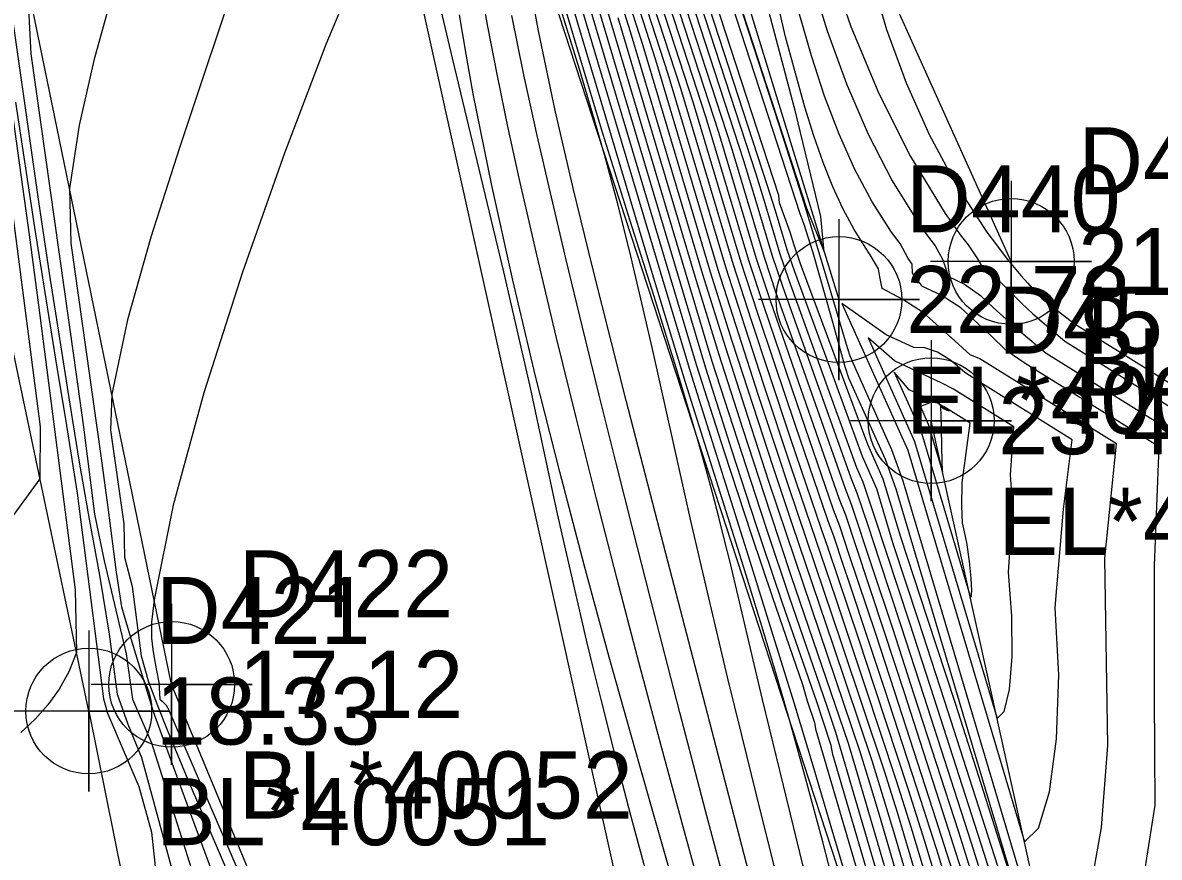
# Model space of a CAD drawing. Extents: x 2356077 to 2359823, y 225951 to 227822.
# Drawn here: x 2356590.47 to 2356632.82, y 227007.67 to 227038.77 of the extents above; entities that cross this region are included whole.
import ezdxf

# ---------------------------------------------------------------- set-up
doc = ezdxf.new("R2010")
doc.units = 0
for name, color, linetype in [('DTM Contours Major', 7, 'Continuous'), ('DTM Contours Minor', 7, 'Continuous'), ('Exist DTM Breakline', 7, 'Continuous'), ('Exist DTM Breakline Cogo Comment', 7, 'Continuous'), ('Exist DTM Breakline Cogo Elevation', 7, 'Continuous'), ('Exist DTM Breakline Cogo Number', 7, 'Continuous'), ('Exist DTM Breakline Cogo Point CELL', 7, 'Continuous'), ('Exist DTM Drainline', 7, 'Continuous'), ('PH Exist DTM Breakline', 7, 'Continuous')]:
    doc.layers.add(name, color=color, linetype=linetype)

msp = doc.modelspace()

# ---------------------------------------------------------------- linework, layer by layer
at = {"layer": 'DTM Contours Major'}
for points in [[(2356626.812, 227007.333), (2356624.819, 227013.515), (2356623.85, 227016.494), (2356622.909, 227019.356), (2356622.297, 227021.404), (2356621.759, 227022.605), (2356620.577, 227025.837), (2356619.238, 227029.489), (2356618.957, 227030.309), (2356618.523, 227031.766), (2356618.228, 227032.691), (2356612.291, 227050.925)], [(2356629.27, 226988.349), (2356629.959, 226992.149), (2356629.673, 226992.804), (2356629.314, 226993.528), (2356629.17, 226994.28), (2356628.968, 226994.95), (2356628.667, 226995.53), (2356628.358, 226996.17), (2356626.282, 227003.244), (2356625.118, 227007.164), (2356624.401, 227009.408), (2356622.955, 227013.857), (2356622.255, 227015.991), (2356621.27, 227018.937), (2356620.919, 227020.011), (2356620.688, 227020.62), (2356619.323, 227024.568), (2356618.094, 227028.184), (2356617.524, 227029.906), (2356615.937, 227035.231), (2356611.325, 227049.397)], [(2356589.642, 227042.057), (2356591.051, 227032.107), (2356591.458, 227029.439), (2356591.872, 227026.773), (2356592.222, 227024.561), (2356592.577, 227022.393), (2356592.945, 227020.266), (2356593.334, 227018.181), (2356593.695, 227015.987), (2356593.982, 227013.751), (2356594.382, 227012.627), (2356594.894, 227011.389), (2356595.263, 227010.019), (2356596.027, 227007.227), (2356596.416, 227005.784), (2356597.076, 227003.228), (2356597.704, 227000.624), (2356598.006, 226998.264), (2356598.808, 226990.945)], [(2356621.331, 226990.471), (2356620.981, 226992.712), (2356620.52, 226995.046), (2356619.978, 226997.442), (2356619.383, 226999.871), (2356618.764, 227002.302), (2356617.178, 227008.439), (2356614.034, 227020.515), (2356612.957, 227024.688), (2356612.404, 227026.855), (2356611.695, 227029.668), (2356610.99, 227032.561), (2356610.315, 227035.506), (2356609.692, 227038.475), (2356609.148, 227041.44)], [(2356620.446, 227041.168), (2356621.329, 227038.631), (2356622.374, 227036.136), (2356623.553, 227033.782), (2356624.843, 227031.665), (2356625.124, 227031.262), (2356625.408, 227030.873), (2356625.697, 227030.498), (2356626.051, 227029.975), (2356626.327, 227029.497), (2356626.867, 227029.144), (2356627.272, 227028.725), (2356627.686, 227028.316), (2356628.108, 227027.917), (2356629.303, 227026.9), (2356635.813, 227022.844)], [(2356625.118, 226990.059), (2356625.172, 226991.585), (2356625.114, 226993.197), (2356625.091, 226993.445), (2356625.048, 226993.939), (2356624.654, 226996.663), (2356620.041, 227012.387), (2356619.989, 227012.675), (2356619.718, 227013.487), (2356619.538, 227014.09), (2356618.423, 227017.334), (2356617.637, 227019.664), (2356616.615, 227022.761), (2356615.572, 227026.025), (2356611.23, 227040.614)], [(2356627.285, 226990.072), (2356627.444, 226991.194), (2356627.654, 226992.353), (2356627.554, 226992.793), (2356627.275, 226993.331), (2356627.145, 226993.984), (2356627.071, 226994.51), (2356626.96, 226995.021), (2356626.852, 226995.234), (2356622.965, 227008.487), (2356622.55, 227009.883), (2356622.117, 227011.259), (2356620.677, 227015.549), (2356619.139, 227020.094), (2356618.433, 227022.216), (2356617.697, 227024.466), (2356616.908, 227026.908), (2356616.099, 227029.474), (2356613.589, 227037.908), (2356612.935, 227039.955)], [(2356623.704, 227023.16), (2356626.776, 227012.842), (2356627.046, 227013.098), (2356627.239, 227013.917), (2356627.338, 227015.153), (2356627.33, 227016.659), (2356627.199, 227018.292), (2356627.368, 227020.71), (2356627.277, 227021.924), (2356627.403, 227023.71), (2356625.158, 227025.109), (2356624.72, 227025.344), (2356622.959, 227026.169), (2356621.971, 227027.028), (2356623.704, 227023.16)]]:
    msp.add_lwpolyline(points, dxfattribs=at)
at = {"layer": 'DTM Contours Minor'}
for points in [[(2356611.415, 227058.105), (2356611.609, 227057.126), (2356612.086, 227055.298), (2356613.972, 227049.36), (2356619.67, 227031.862), (2356620.339, 227030.237), (2356620.206, 227031.548), (2356619.267, 227035.452), (2356615.488, 227049.719), (2356613.555, 227055.854), (2356615.374, 227056.83), (2356611.817, 227058.329), (2356611.415, 227058.105)], [(2356627.237, 227004.773), (2356626.311, 227007.775), (2356624.438, 227013.594), (2356623.526, 227016.398), (2356622.655, 227019.028), (2356622.226, 227020.34), (2356621.786, 227021.65), (2356621.552, 227022.186), (2356620.526, 227025.03), (2356619.013, 227029.207), (2356618.685, 227030.179), (2356618.131, 227032.039), (2356617.794, 227033.127), (2356611.142, 227053.555)], [(2356626.691, 227005.425), (2356625.823, 227008.197), (2356624.062, 227013.664), (2356623.205, 227016.297), (2356622.392, 227018.743), (2356621.984, 227019.996), (2356621.569, 227021.24), (2356621.337, 227021.792), (2356619.249, 227027.648), (2356618.792, 227028.937), (2356618.394, 227030.112), (2356617.725, 227032.361), (2356617.337, 227033.631), (2356610.893, 227053.422)], [(2356630.311, 226988.925), (2356630.88, 226992.059), (2356630.519, 226992.812), (2356630.153, 226993.591), (2356629.979, 226994.385), (2356629.711, 226995.156), (2356628.936, 226996.651), (2356628.636, 226997.649), (2356627.36, 227001.998), (2356626.161, 227006.025), (2356625.347, 227008.604), (2356623.694, 227013.727), (2356622.891, 227016.19), (2356622.125, 227018.492), (2356621.356, 227020.822), (2356621.124, 227021.398), (2356619.051, 227027.271), (2356618.551, 227028.699), (2356618.111, 227030.022), (2356617.319, 227032.68), (2356616.879, 227034.138), (2356610.734, 227053.011)], [(2356629.791, 226988.638), (2356630.42, 226992.105), (2356630.095, 226992.809), (2356629.733, 226993.562), (2356629.574, 226994.334), (2356629.34, 226995.053), (2356628.997, 226995.714), (2356628.645, 226996.404), (2356626.82, 227002.624), (2356625.636, 227006.605), (2356624.871, 227009.009), (2356623.323, 227013.793), (2356622.572, 227016.09), (2356621.508, 227019.291), (2356621.137, 227020.418), (2356620.906, 227021.007), (2356619.377, 227025.387), (2356618.324, 227028.44), (2356617.815, 227029.97), (2356616.407, 227034.687), (2356610.598, 227052.532)], [(2356632.386, 226990.036), (2356632.711, 226991.826), (2356632.232, 226992.787), (2356631.801, 226993.685), (2356631.539, 226994.644), (2356631.141, 226995.676), (2356630.047, 226997.786), (2356629.946, 226998.035), (2356629.913, 226998.396), (2356629.592, 226999.277), (2356629.488, 226999.576), (2356627.346, 227006.768), (2356626.29, 227010.101), (2356625.224, 227013.397), (2356624.19, 227016.563), (2356623.188, 227019.6), (2356622.537, 227021.76), (2356621.96, 227023.05), (2356619.458, 227029.792), (2356619.216, 227030.481), (2356619.071, 227030.97), (2356618.673, 227032.063), (2356618.64, 227032.327), (2356612.488, 227051.222)], [(2356628.749, 226988.06), (2356629.498, 226992.19), (2356629.251, 226992.799), (2356628.896, 226993.493), (2356628.765, 226994.224), (2356628.596, 226994.848), (2356628.338, 226995.344), (2356628.067, 226995.945), (2356625.248, 227005.545), (2356624.603, 227007.712), (2356623.935, 227009.798), (2356622.589, 227013.92), (2356621.938, 227015.894), (2356621.311, 227017.77), (2356621.026, 227018.613), (2356620.703, 227019.6), (2356620.469, 227020.238), (2356619.26, 227023.763), (2356618.478, 227026.084), (2356617.861, 227027.93), (2356617.236, 227029.83), (2356615.466, 227035.775), (2356611.129, 227049.1)], [(2356614.528, 227046.719), (2356619.432, 227031.658), (2356619.571, 227031.259), (2356619.73, 227030.789), (2356619.911, 227030.209), (2356620.595, 227027.797), (2356621.107, 227025.959), (2356621.244, 227025.542), (2356622.602, 227022.508), (2356623.005, 227021.395), (2356628.693, 227002.292)], [(2356614.819, 227046.725), (2356618.644, 227034.976), (2356619.571, 227032.059), (2356620.413, 227029.299), (2356621.159, 227026.796), (2356621.277, 227026.391), (2356621.409, 227026.067), (2356622.845, 227022.862), (2356623.267, 227021.698), (2356627.902, 227006.131)], [(2356603.142, 227041.249), (2356601.769, 227037.958), (2356600.222, 227033.916), (2356598.654, 227029.474), (2356597.22, 227024.984), (2356596.073, 227020.796), (2356595.369, 227017.263), (2356595.271, 227016.435), (2356595.262, 227015.837), (2356595.314, 227015.413), (2356595.383, 227015.021), (2356595.459, 227014.631), (2356595.537, 227014.182), (2356595.576, 227013.567), (2356595.665, 227013.492), (2356595.743, 227013.417), (2356595.81, 227013.337), (2356595.867, 227013.251), (2356595.915, 227013.156), (2356601.009, 227001.351)], [(2356618.392, 226987.922), (2356617.47, 226991.783), (2356614.336, 227004.774), (2356613.131, 227009.221), (2356612.569, 227011.373), (2356612.022, 227013.546), (2356611.751, 227014.648), (2356611.483, 227015.766), (2356610.402, 227020.473), (2356609.361, 227025.273), (2356608.402, 227029.494), (2356606.482, 227037.446), (2356605.533, 227041.515)], [(2356623.747, 226990.674), (2356623.688, 226991.839), (2356623.575, 226993.042), (2356623.411, 226994.29), (2356623.202, 226995.588), (2356622.95, 226996.943), (2356622.662, 226998.36), (2356622.133, 227000.76), (2356621.544, 227003.259), (2356620.918, 227005.781), (2356620.281, 227008.247), (2356619.654, 227010.582), (2356619.064, 227012.707), (2356618.562, 227014.451), (2356618.065, 227016.115), (2356617.326, 227018.507), (2356615.164, 227025.366), (2356614.016, 227029.166), (2356610.39, 227041.347)], [(2356628.546, 226989.523), (2356629.037, 226992.23), (2356628.828, 226992.794), (2356628.486, 226993.453), (2356628.36, 226994.166), (2356628.222, 226994.75), (2356628.01, 226995.159), (2356627.774, 226995.733), (2356624.677, 227006.281), (2356624.09, 227008.253), (2356623.473, 227010.18), (2356622.225, 227013.981), (2356621.623, 227015.801), (2356620.488, 227019.185), (2356620.249, 227019.864), (2356619.095, 227023.253), (2356618.284, 227025.685), (2356617.625, 227027.676), (2356616.95, 227029.746), (2356614.995, 227036.315), (2356613.371, 227041.316)], [(2356598.672, 227041.19), (2356596.305, 227034.112), (2356595.244, 227030.783), (2356594.377, 227027.696), (2356593.788, 227024.93), (2356593.741, 227023.59), (2356594.236, 227020.096), (2356594.26, 227018.853), (2356594.548, 227017.759), (2356594.879, 227015.181), (2356595.156, 227014.203), (2356595.489, 227013.327), (2356595.851, 227012.42), (2356596.675, 227010.441), (2356598.524, 227006.146)], [(2356622.979, 226989.938), (2356622.876, 226991.413), (2356622.693, 226992.944), (2356622.441, 226994.53), (2356622.131, 226996.172), (2356621.775, 226997.871), (2356621.383, 226999.625), (2356620.825, 227002.034), (2356620.242, 227004.484), (2356619.077, 227009.279), (2356618.037, 227013.552), (2356616.825, 227018.662), (2356616.623, 227019.492), (2356616.408, 227020.347), (2356616.172, 227021.248), (2356615.91, 227022.214), (2356615.612, 227023.262), (2356614.869, 227025.747), (2356613.994, 227028.571), (2356613.035, 227031.626), (2356612.041, 227034.81), (2356611.038, 227038.127), (2356610.146, 227041.14)], [(2356621.026, 227007.339), (2356620.497, 227009.137), (2356619.957, 227010.95), (2356619.21, 227013.419), (2356618.385, 227016.098), (2356617.512, 227018.891), (2356615.4, 227025.599), (2356614.293, 227029.28), (2356610.809, 227040.986)], [(2356630.204, 227006.189), (2356630.666, 227008.78), (2356630.9, 227011.83), (2356630.796, 227018.813), (2356631.222, 227023.08), (2356626.141, 227026.246), (2356625.77, 227026.395), (2356625.199, 227026.917), (2356624.034, 227027.966), (2356623.271, 227028.46), (2356622.501, 227028.867), (2356622.404, 227029.297), (2356622.356, 227029.604), (2356622.206, 227029.848), (2356622.053, 227030.125), (2356621.885, 227030.368), (2356621.453, 227031.065), (2356621.046, 227031.828), (2356620.663, 227032.661), (2356620.298, 227033.568), (2356619.949, 227034.554), (2356619.611, 227035.622), (2356618.898, 227038.245), (2356618.23, 227041.128)], [(2356619.809, 226989.477), (2356619.263, 226992.535), (2356618.508, 226995.721), (2356617.714, 226999.013), (2356616.886, 227002.231), (2356615.121, 227008.667), (2356614.252, 227011.874), (2356613.384, 227015.126), (2356612.621, 227018.033), (2356611.852, 227021.022), (2356611.088, 227024.053), (2356610.345, 227027.084), (2356609.634, 227030.074), (2356608.968, 227032.984), (2356608.547, 227034.91), (2356608.155, 227036.788), (2356607.797, 227038.626), (2356607.475, 227040.435)], [(2356619.82, 227040.489), (2356620.446, 227038.468), (2356621.167, 227036.497), (2356621.976, 227034.622), (2356622.866, 227032.883), (2356623.831, 227031.323), (2356624.146, 227030.879), (2356624.468, 227030.455), (2356624.75, 227029.966), (2356624.972, 227029.309), (2356625.563, 227029.032), (2356626.158, 227028.608), (2356626.635, 227028.159), (2356627.123, 227027.716), (2356627.621, 227027.273), (2356628.612, 227026.456), (2356634.261, 227022.936)], [(2356622.08, 227040.478), (2356622.654, 227038.515), (2356623.39, 227036.537), (2356624.244, 227034.606), (2356625.252, 227032.735), (2356626.398, 227030.969), (2356626.751, 227030.489), (2356626.931, 227030.253), (2356627.171, 227029.949), (2356627.415, 227029.65), (2356627.664, 227029.356), (2356627.918, 227029.065), (2356628.177, 227028.778), (2356628.44, 227028.494), (2356629.646, 227027.562), (2356637.397, 227022.732)], [(2356590.628, 227040.262), (2356590.765, 227037.615), (2356592.359, 227026.365), (2356592.727, 227023.696), (2356593.143, 227020.456), (2356593.501, 227018.716), (2356594.32, 227015.248), (2356594.556, 227013.567), (2356595.261, 227011.932), (2356595.791, 227010.279), (2356596.305, 227008.643), (2356596.82, 227007.029), (2356597.321, 227005.352), (2356597.804, 227003.681), (2356598.33, 227001.705), (2356598.815, 226999.717), (2356599.258, 226997.742), (2356599.659, 226995.807), (2356600.019, 226993.939), (2356600.291, 226992.119), (2356600.644, 226989.968)], [(2356622.1, 226990.921), (2356621.835, 226992.793), (2356621.48, 226994.741), (2356621.054, 226996.753), (2356620.576, 226998.818), (2356620.065, 227000.926), (2356618.941, 227005.464), (2356617.812, 227009.996), (2356617.264, 227012.215), (2356616.738, 227014.376), (2356616.035, 227017.334), (2356615.371, 227020.205), (2356614.728, 227023.055), (2356613.92, 227026.67), (2356613.505, 227028.481), (2356613.076, 227030.282), (2356612.63, 227032.063), (2356612.16, 227033.817), (2356611.693, 227035.44), (2356611.211, 227037.041), (2356610.239, 227040.215)], [(2356625.548, 226989.87), (2356625.611, 226991.242), (2356625.845, 226992.714), (2356625.786, 226992.924), (2356625.635, 226993.261), (2356625.555, 226993.629), (2356625.468, 226994.067), (2356625.379, 226994.793), (2356624.924, 226996.954), (2356620.656, 227011.504), (2356620.6, 227011.828), (2356620.291, 227012.741), (2356620.056, 227013.461), (2356618.786, 227017.134), (2356618.037, 227019.35), (2356617.802, 227020.057), (2356616.894, 227022.836), (2356615.922, 227025.896), (2356611.723, 227040.002)], [(2356626.849, 226989.986), (2356626.966, 226991.146), (2356627.195, 226992.405), (2356627.125, 226992.8), (2356626.866, 226993.299), (2356626.738, 226993.921), (2356626.653, 226994.514), (2356626.572, 226995.013), (2356626.512, 226995.182), (2356622.39, 227009.233), (2356622.033, 227010.435), (2356621.676, 227011.593), (2356618.937, 227019.682), (2356618.274, 227021.679), (2356617.5, 227024.055), (2356616.665, 227026.651), (2356615.813, 227029.39), (2356613.122, 227038.431), (2356612.521, 227040.328)], [(2356593.788, 227039.798), (2356593.117, 227037.359), (2356592.574, 227034.953), (2356592.208, 227032.596), (2356592.259, 227030.558), (2356593.384, 227022.624), (2356593.641, 227020.702), (2356593.95, 227018.296), (2356594.153, 227016.999), (2356594.532, 227015.693), (2356595.334, 227013.105), (2356596.027, 227011.188), (2356596.721, 227009.286), (2356598.145, 227005.437), (2356598.926, 227003.493), (2356599.479, 227001.592), (2356599.954, 227000.07), (2356600.393, 226998.56), (2356600.799, 226997.062), (2356601.177, 226995.578), (2356601.531, 226994.106), (2356601.866, 226992.647), (2356602.148, 226991.078), (2356602.905, 226986.477)], [(2356627.726, 226990.167), (2356628.114, 226992.309), (2356627.98, 226992.79), (2356627.68, 226993.369), (2356627.55, 226994.046), (2356627.463, 226994.575), (2356627.35, 226994.792), (2356627.17, 226995.365), (2356623.537, 227007.747), (2356623.064, 227009.336), (2356622.564, 227010.911), (2356620.992, 227015.627), (2356619.017, 227021.472), (2356618.591, 227022.752), (2356617.893, 227024.875), (2356617.149, 227027.165), (2356616.383, 227029.564), (2356614.056, 227037.381), (2356613.351, 227039.577)], [(2356625.981, 226989.866), (2356626.044, 226991.131), (2356626.287, 226992.568), (2356626.25, 226992.85), (2356626.03, 226993.274), (2356625.92, 226993.787), (2356625.866, 226994.252), (2356625.802, 226994.725), (2356625.729, 226995.206), (2356625.252, 226997.049), (2356620.995, 227011.56), (2356620.77, 227012.314), (2356620.442, 227013.288), (2356619.042, 227017.365), (2356618.218, 227019.813), (2356617.958, 227020.6), (2356617.1, 227023.235), (2356616.166, 227026.148), (2356615.23, 227029.264), (2356612.19, 227039.475)], [(2356628.219, 226990.305), (2356628.575, 226992.269), (2356628.405, 226992.791), (2356628.084, 226993.41), (2356627.956, 226994.107), (2356627.845, 226994.657), (2356627.681, 226994.974), (2356627.475, 226995.537), (2356624.107, 227007.014), (2356623.577, 227008.794), (2356623.016, 227010.551), (2356621.863, 227014.041), (2356620.767, 227017.32), (2356619.108, 227022.211), (2356618.089, 227025.282), (2356617.388, 227027.421), (2356616.666, 227029.656), (2356614.525, 227036.85), (2356613.768, 227039.195)], [(2356632.257, 227006.999), (2356632.669, 227009.609), (2356632.644, 227013.674), (2356632.64, 227018.545), (2356632.816, 227022.962), (2356627.82, 227026.075), (2356627.12, 227026.551), (2356626.54, 227027.111), (2356625.421, 227028.152), (2356624.699, 227028.614), (2356624.001, 227028.941), (2356623.624, 227029.439), (2356623.611, 227029.774), (2356623.459, 227029.979), (2356623.161, 227030.541), (2356622.991, 227030.767), (2356622.824, 227030.999), (2356622.125, 227032.094), (2356621.482, 227033.302), (2356620.891, 227034.618), (2356620.35, 227036.032), (2356619.857, 227037.538), (2356619.407, 227039.129)], [(2356589.598, 227038.738), (2356590.712, 227030.873), (2356591.062, 227028.245), (2356592.424, 227017.633), (2356592.469, 227015.306), (2356592.184, 227014.579), (2356591.828, 227013.932), (2356591.407, 227013.348), (2356590.927, 227012.814), (2356590.395, 227012.313)], [(2356619.091, 226988.889), (2356618.352, 226992.245), (2356616.509, 226999.891), (2356615.642, 227003.449), (2356613.463, 227011.077), (2356612.707, 227013.764), (2356612.327, 227015.131), (2356611.405, 227018.519), (2356610.481, 227022.029), (2356609.581, 227025.601), (2356608.727, 227029.178), (2356607.946, 227032.703), (2356607.26, 227036.116), (2356606.989, 227037.605), (2356606.741, 227039.069)], [(2356620.559, 226989.995), (2356620.11, 226992.636), (2356619.529, 226995.394), (2356618.856, 226998.216), (2356618.13, 227001.049), (2356615.917, 227009.405), (2356614.96, 227013.059), (2356613.85, 227017.357), (2356613.215, 227019.846), (2356612.581, 227022.362), (2356611.951, 227024.891), (2356611.33, 227027.421), (2356610.722, 227029.938), (2356610.169, 227032.27), (2356609.641, 227034.572), (2356609.148, 227036.833), (2356608.699, 227039.047)], [(2356626.414, 226989.914), (2356626.491, 226991.108), (2356626.738, 226992.473), (2356626.692, 226992.817), (2356626.453, 226993.278), (2356626.33, 226993.856), (2356626.26, 226994.394), (2356626.177, 226994.944), (2356626.115, 226995.322), (2356621.515, 227010.994), (2356621.241, 227011.912), (2356619.11, 227018.16), (2356618.329, 227020.492), (2356617.301, 227023.643), (2356616.418, 227026.396), (2356615.524, 227029.318), (2356612.656, 227038.953)], [(2356590.202, 227035.812), (2356590.913, 227031.14), (2356591.288, 227028.719), (2356591.686, 227026.232), (2356592.103, 227023.755), (2356592.492, 227021.234), (2356593.475, 227013.573), (2356593.622, 227013.045), (2356594.801, 227010.312), (2356595.262, 227008.609), (2356595.745, 227004.198), (2356595.804, 227002.729), (2356595.263, 227001.537), (2356594.411, 227000.438), (2356593.292, 226999.429), (2356591.968, 226998.499), (2356590.499, 226997.637), (2356588.948, 226996.831)], [(2356590.078, 227031.784), (2356591.115, 227023.708), (2356591.109, 227021.768), (2356589.905, 227020.117)], [(2356623.448, 227022.836), (2356627.794, 227008.242), (2356628.323, 227008.753), (2356628.734, 227010.11), (2356628.994, 227012.086), (2356629.073, 227014.452), (2356628.938, 227016.979), (2356629.249, 227020.64), (2356629.577, 227023.231), (2356626.231, 227025.316), (2356625.581, 227025.738), (2356625.057, 227026.189), (2356624.555, 227026.496), (2356624.089, 227026.656), (2356623.672, 227026.668), (2356622.644, 227027.141), (2356620.998, 227028.308), (2356623.448, 227022.836)], [(2356623.959, 227023.483), (2356625.759, 227017.441), (2356625.812, 227017.368), (2356625.833, 227017.601), (2356625.815, 227018.066), (2356625.755, 227018.691), (2356625.649, 227019.403), (2356625.491, 227020.13), (2356625.465, 227020.769), (2356625.48, 227021.625), (2356625.77, 227023.852), (2356624.803, 227024.455), (2356624.533, 227024.608), (2356623.497, 227025.094), (2356622.945, 227025.748), (2356623.959, 227023.483)], [(2356624.215, 227023.806), (2356624.741, 227022.04), (2356624.723, 227022.914), (2356624.701, 227023.727), (2356624.676, 227024.486), (2356624.777, 227024.396), (2356624.881, 227024.344), (2356624.991, 227024.303), (2356624.64, 227024.522), (2356624.556, 227024.754), (2356624.479, 227024.601), (2356624.376, 227024.649), (2356623.918, 227024.468), (2356624.215, 227023.806)]]:
    msp.add_lwpolyline(points, dxfattribs=at)
at = {"layer": 'Exist DTM Breakline'}
for p, q in [((2356611.87, 227057.862), (2356620.885, 227028.455)), ((2356627.301, 227029.877), (2356617.949, 227050.619)), ((2356608.68, 227044.456), (2356625.567, 226992.825)), ((2356630.061, 226997.999), (2356624.32, 227023.94))]:
    msp.add_line(p, q, dxfattribs=at)
for points in [[(2356592.929, 227013.119), (2356584.678, 227052.34), (2356580.201, 227083.43), (2356576.451, 227102.549), (2356583.173, 227120.277), (2356590.413, 227117.802), (2356595.556, 227101.99), (2356603.689, 227072.972), (2356610.454, 227075.196)], [(2356596.018, 227014.113), (2356588.008, 227052.967), (2356582.396, 227083.926), (2356581.788, 227104.479), (2356583.994, 227108.268), (2356586.417, 227103.404), (2356591.309, 227091.366), (2356596.499, 227069.437), (2356605.464, 227067.142)]]:
    msp.add_lwpolyline(points, dxfattribs=at)
at = {"layer": 'Exist DTM Breakline Cogo Point CELL'}
for points in [[(2356627.301, 227032.877), (2356627.301, 227026.877), (2356627.301, 227029.877), (2356630.301, 227029.877), (2356624.301, 227029.877)], [(2356620.885, 227031.455), (2356620.885, 227025.455), (2356620.885, 227028.455), (2356623.885, 227028.455), (2356617.885, 227028.455)], [(2356624.32, 227026.94), (2356624.32, 227020.94), (2356624.32, 227023.94), (2356627.32, 227023.94), (2356621.32, 227023.94)], [(2356596.018, 227017.113), (2356596.018, 227011.113), (2356596.018, 227014.113), (2356599.018, 227014.113), (2356593.018, 227014.113)], [(2356592.929, 227016.119), (2356592.929, 227010.119), (2356592.929, 227013.119), (2356595.929, 227013.119), (2356589.929, 227013.119)]]:
    msp.add_lwpolyline(points, dxfattribs=at)
for centre in [(2356627.301, 227029.877), (2356620.885, 227028.455), (2356624.32, 227023.94), (2356596.018, 227014.113), (2356592.929, 227013.119)]:
    msp.add_circle(centre, 2.344, dxfattribs=at)
at = {"layer": 'Exist DTM Drainline'}
msp.add_lwpolyline([(2356611.124, 227064.552), (2356604.524, 227061.802), (2356604.825, 227041.806), (2356618.493, 226980.155)], dxfattribs=at)
at = {"layer": 'PH Exist DTM Breakline'}
for points in [[(2356612.018, 226955.496), (2356609.235, 226973.835), (2356603.789, 226995.38), (2356596.018, 227014.113)], [(2356592.929, 227013.119), (2356597.662, 226989.631), (2356604.261, 226965.187), (2356610.155, 226942.179), (2356615.045, 226919.444), (2356623.632, 226894.144)]]:
    msp.add_lwpolyline(points, dxfattribs=at)

# ---------------------------------------------------------------- texts
at = {"layer": 'Exist DTM Breakline Cogo Comment'}
for s, p in [('BL*40051', (2356629.801, 227024.877)), ('EL*40051', (2356623.385, 227023.456)), ('EL*40051', (2356626.82, 227018.94)), ('BL*40052', (2356598.518, 227009.113)), ('BL*40051', (2356595.429, 227008.119))]:
    msp.add_text(s, height=2.5, dxfattribs=at).set_placement(p)
at = {"layer": 'Exist DTM Breakline Cogo Elevation'}
for s, p in [('21.70', (2356629.801, 227028.627)), ('22.78', (2356623.385, 227027.206)), ('23.48', (2356626.82, 227022.69)), ('17.12', (2356598.518, 227012.863)), ('18.33', (2356595.429, 227011.869))]:
    msp.add_text(s, height=2.5, dxfattribs=at).set_placement(p)
at = {"layer": 'Exist DTM Breakline Cogo Number'}
for s, p in [('D441', (2356629.801, 227032.377)), ('D440', (2356623.385, 227030.956)), ('D451', (2356626.82, 227026.44)), ('D422', (2356598.518, 227016.613)), ('D421', (2356595.429, 227015.619))]:
    msp.add_text(s, height=2.5, dxfattribs=at).set_placement(p)

doc.saveas('drawing.dxf')
